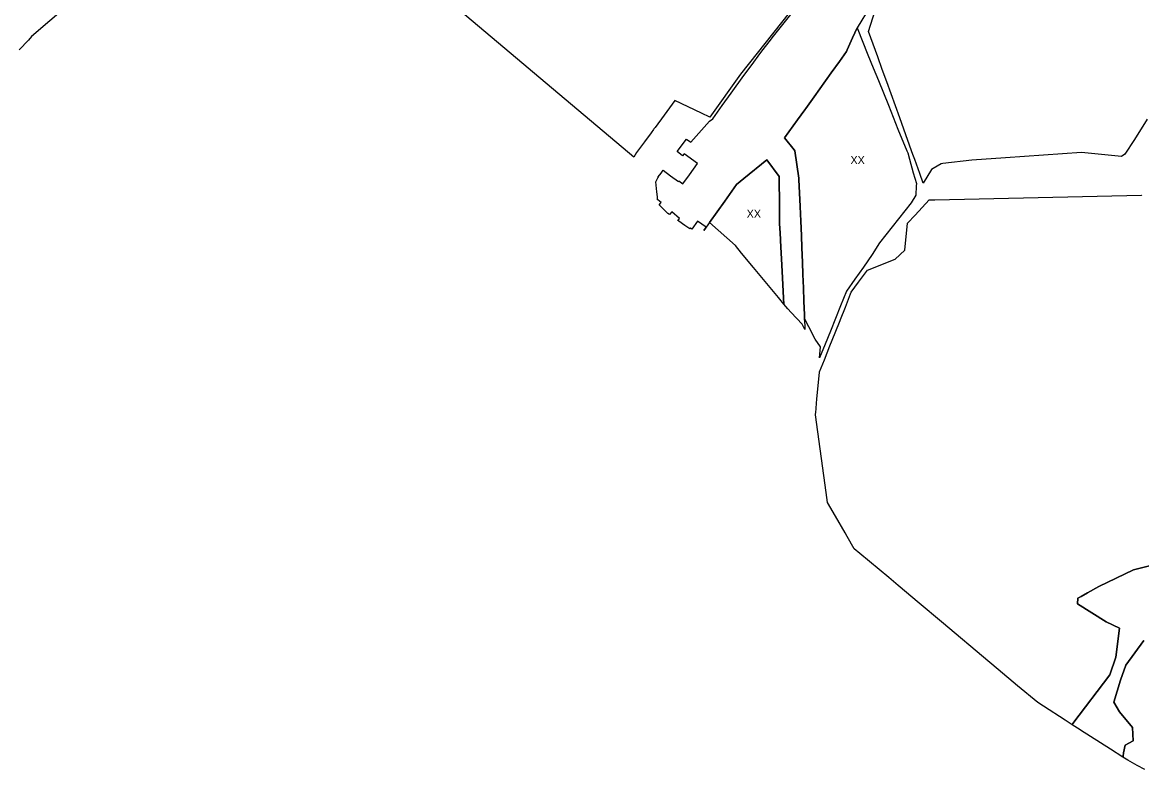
# Model space of a CAD drawing. Extents: x -537068 to -534056, y -1176840 to -1172401.
# Drawn here: x -536233 to -535534, y -1176810 to -1176344 of the extents above; entities that cross this region are included whole.
import ezdxf

# ---------------------------------------------------------------- set-up
doc = ezdxf.new("R2010")
doc.units = 0
for name, color, linetype in [('90550013', 7, 'Continuous'), ('90640013', 7, 'Continuous'), ('90710023', 7, 'Continuous'), ('90730013', 7, 'Continuous'), ('90750013', 7, 'Continuous')]:
    doc.layers.add(name, color=color, linetype=linetype)

msp = doc.modelspace()

# ---------------------------------------------------------------- linework, layer by layer
at = {"layer": '90550013'}
msp.add_lwpolyline([(-535530.06, -1176404.25), (-535538.13, -1176416.77), (-535544.12, -1176426.06), (-535546.07, -1176427.53), (-535571.1, -1176424.91), (-535618.53, -1176428.31), (-535639.55, -1176429.82), (-535657.85, -1176431.79), (-535658.77, -1176432.03), (-535663.81, -1176434.93), (-535664.74, -1176435.61), (-535669.94, -1176444.21), (-535672.16, -1176438.09), (-535675.32, -1176429.34), (-535676.47, -1176426.16), (-535677.31, -1176423.83), (-535682.13, -1176410.42), (-535684.69, -1176403.31), (-535687.39, -1176395.81), (-535692.81, -1176380.73), (-535695.55, -1176373.11), (-535698.43, -1176365.11), (-535704.11, -1176349.3), (-535700.03, -1176336.26)], dxfattribs=at)
for points in [[(-535674.59, -1176451.72), (-535677.45, -1176456.39), (-535697.41, -1176481.4), (-535701.92, -1176488.79), (-535707.35, -1176496.57), (-535712.69, -1176504.06), (-535718.01, -1176511.69), (-535721.59, -1176520.75), (-535724.82, -1176528.73), (-535727.94, -1176536.52), (-535731.3, -1176544.75), (-535734.75, -1176553.24), (-535734.17, -1176546.44), (-535737.41, -1176541.67), (-535741.44, -1176533.9), (-535743.29, -1176530.39), (-535743.81, -1176529.37), (-535744.12, -1176529.72), (-535744.24, -1176526.34), (-535744.54, -1176517.8), (-535744.83, -1176509.58), (-535745.13, -1176501.16), (-535745.4, -1176493.4), (-535745.72, -1176484.46), (-535746.06, -1176476.88), (-535746.47, -1176467.8), (-535746.87, -1176458.77), (-535747.63, -1176441.81), (-535747.75, -1176441), (-535750.23, -1176423.85), (-535750.71, -1176423.25), (-535756.58, -1176415.83), (-535748.51, -1176404.56), (-535743.99, -1176398.26), (-535743.37, -1176397.4), (-535738.21, -1176390.2), (-535727.54, -1176375.3), (-535722.39, -1176368.11), (-535717.9, -1176361.84), (-535717.46, -1176360.86), (-535714.08, -1176353.32), (-535711.31, -1176347.15), (-535704.53, -1176363.92), (-535701.24, -1176372.05), (-535698.04, -1176379.96), (-535691.75, -1176395.49), (-535688.76, -1176402.9), (-535685.77, -1176410.3), (-535680.29, -1176423.83), (-535679.7, -1176425.28), (-535678.58, -1176429.21), (-535676.19, -1176437.59), (-535674.3, -1176444.24), (-535674.36, -1176445.88)], [(-535756.96, -1176519.78), (-535760.42, -1176515.6), (-535768.68, -1176505.62), (-535775.96, -1176496.83), (-535783.4, -1176487.84), (-535787.33, -1176483.09), (-535803.54, -1176468.74), (-535798.79, -1176462.08), (-535793.96, -1176455.31), (-535786.56, -1176444.94), (-535781.98, -1176441.22), (-535767.68, -1176429.62), (-535760.01, -1176440.02), (-535760, -1176441.08), (-535759.81, -1176457.82), (-535759.72, -1176466.35), (-535759.68, -1176469.54), (-535759.38, -1176475.26), (-535758.91, -1176484.13), (-535758.51, -1176491.48), (-535758.08, -1176499.34), (-535757.64, -1176507.45), (-535757.17, -1176516.05)]]:
    msp.add_lwpolyline(points, close=True, dxfattribs=at)
at = {"layer": '90640013'}
for points in [[(-535703.24, -1176333.84), (-535711.31, -1176347.15), (-535714.08, -1176353.32), (-535717.46, -1176360.86), (-535717.9, -1176361.84), (-535722.39, -1176368.11), (-535727.54, -1176375.3), (-535738.21, -1176390.2), (-535743.37, -1176397.4), (-535743.99, -1176398.26), (-535748.51, -1176404.56), (-535756.58, -1176415.83), (-535750.71, -1176423.25), (-535750.23, -1176423.85), (-535747.75, -1176441), (-535747.63, -1176441.81), (-535746.87, -1176458.77), (-535746.47, -1176467.8), (-535746.06, -1176476.88), (-535745.72, -1176484.46), (-535745.4, -1176493.4), (-535745.13, -1176501.16), (-535744.83, -1176509.58), (-535744.54, -1176517.8), (-535744.24, -1176526.34), (-535744.12, -1176529.72), (-535743.96, -1176534.12), (-535743.9, -1176535.62), (-535744.79, -1176533.92), (-535745.69, -1176532.19), (-535752.39, -1176525), (-535754.65, -1176522.57), (-535756.96, -1176519.78), (-535757.17, -1176516.05), (-535757.64, -1176507.45), (-535758.08, -1176499.34), (-535758.51, -1176491.48), (-535758.91, -1176484.13), (-535759.38, -1176475.26), (-535759.68, -1176469.54), (-535759.72, -1176466.35), (-535759.81, -1176457.82), (-535760, -1176441.08), (-535760.01, -1176440.02), (-535767.68, -1176429.62), (-535781.98, -1176441.22), (-535786.56, -1176444.94), (-535793.96, -1176455.31), (-535798.79, -1176462.08), (-535803.54, -1176468.74), (-535807.04, -1176473.64), (-535805.66, -1176471.65), (-535810.99, -1176467.85), (-535814.51, -1176472.78), (-535815.39, -1176472.01), (-535815.79, -1176472.66), (-535818.84, -1176470.52), (-535820.4, -1176469.45), (-535823.43, -1176467.31), (-535823.13, -1176467.38), (-535822.14, -1176466.2), (-535826.97, -1176462.05), (-535828.46, -1176463.79), (-535829.43, -1176463.13), (-535834.99, -1176457.72), (-535833.71, -1176456.25), (-535835.85, -1176454.59), (-535836.06, -1176454.57), (-535835.98, -1176452.6), (-535836.3, -1176449.47), (-535836.91, -1176443.39), (-535835.7, -1176440.88), (-535835.37, -1176440.19), (-535835.49, -1176440.1), (-535833.72, -1176437.83), (-535832.45, -1176436.05), (-535827.81, -1176439.46), (-535822.86, -1176443.09), (-535822.57, -1176442.7), (-535820.19, -1176444.54), (-535815.92, -1176438.86), (-535810.92, -1176431.84), (-535819.35, -1176425.76), (-535820.26, -1176426.99), (-535823.71, -1176424.37), (-535817.82, -1176416.66), (-535815.25, -1176418.52), (-535803.56, -1176405.4), (-535801.4, -1176403.85), (-535795.48, -1176395.6), (-535789.9, -1176387.82), (-535782.02, -1176376.84), (-535777.52, -1176370.83), (-535771.34, -1176362.59), (-535764.83, -1176353.9), (-535764.34, -1176353.29), (-535752.68, -1176338.75)], [(-535510.43, -1176678.69), (-535538.74, -1176685.61), (-535560.3, -1176696.02), (-535567.5, -1176700.1), (-535571.31, -1176702.26), (-535573.45, -1176703.47), (-535573.71, -1176706.9), (-535555.67, -1176718.13), (-535547.5, -1176722.15), (-535549.75, -1176740.16), (-535553.5, -1176751.27), (-535576.51, -1176781.66), (-535576.91, -1176782.46), (-535581.44, -1176779.56), (-535594.9, -1176770.95), (-535598.48, -1176768.66), (-535611.07, -1176758.1), (-535623.22, -1176747.9), (-535628.42, -1176743.54), (-535658.68, -1176718.16), (-535672.54, -1176706.53), (-535685.74, -1176695.46), (-535691.56, -1176690.57), (-535709.56, -1176675.47), (-535713.04, -1176672.55), (-535717.46, -1176664.91), (-535718.78, -1176662.62), (-535724.88, -1176652.06), (-535729.7, -1176643.72), (-535730.58, -1176637.35), (-535737.27, -1176588.86), (-535737.19, -1176588), (-535737.15, -1176587.55), (-535736.36, -1176578.79), (-535735.61, -1176570.64), (-535734.85, -1176562.23), (-535734.72, -1176561.9), (-535731.73, -1176554.4), (-535728.31, -1176545.84), (-535725.02, -1176537.6), (-535721.93, -1176529.86), (-535721.7, -1176529.29), (-535718.6, -1176521.51), (-535715.34, -1176513.34), (-535714.92, -1176512.29), (-535710.34, -1176505.96), (-535705.52, -1176499.3), (-535704.9, -1176498.43), (-535704.8, -1176498.45), (-535687.44, -1176491.61), (-535681.47, -1176485.96), (-535679.85, -1176469.17), (-535675.08, -1176464.08), (-535666.19, -1176454.59), (-535662.84, -1176454.52), (-535533.71, -1176451.64), (-535533.49, -1176451.75)], [(-535531.67, -1176810.49), (-535536.29, -1176807.93), (-535542.25, -1176804.63), (-535545.34, -1176802.66), (-535545.23, -1176802.1), (-535544.85, -1176800.08), (-535543.92, -1176795.2), (-535538.92, -1176792.48), (-535539.33, -1176784.21), (-535547.44, -1176774.42), (-535550.96, -1176768.35), (-535546.78, -1176754.69), (-535543.5, -1176745.17), (-535532.18, -1176729.85)]]:
    msp.add_lwpolyline(points, dxfattribs=at)
at = {"layer": '90710023'}
msp.add_lwpolyline([(-536179.68, -1176311.98), (-536226.88, -1176352.57), (-536228.89, -1176354.7), (-536234.72, -1176360.87)], dxfattribs=at)
at = {"layer": '90730013'}
msp.add_lwpolyline([(-535532.18, -1176729.85), (-535543.5, -1176745.17), (-535546.78, -1176754.69), (-535550.96, -1176768.35), (-535547.44, -1176774.42), (-535539.33, -1176784.21), (-535538.92, -1176792.48), (-535543.92, -1176795.2), (-535544.85, -1176800.08), (-535545.23, -1176802.1), (-535545.34, -1176802.66), (-535553.07, -1176797.71), (-535571.69, -1176785.8), (-535572.06, -1176785.56), (-535573.58, -1176784.59), (-535576.91, -1176782.46), (-535576.51, -1176781.66), (-535553.5, -1176751.27), (-535549.75, -1176740.16), (-535547.5, -1176722.15), (-535555.67, -1176718.13), (-535573.71, -1176706.9), (-535573.45, -1176703.47), (-535571.31, -1176702.26), (-535567.5, -1176700.1), (-535560.3, -1176696.02), (-535538.74, -1176685.61), (-535510.43, -1176678.69)], dxfattribs=at)
at = {"layer": '90750013'}
msp.add_lwpolyline([(-535743.34, -1176324.33), (-535784.04, -1176376), (-535803.32, -1176402.89), (-535803.35, -1176402.91), (-535808.48, -1176400.44), (-535825.21, -1176392.4), (-535831.85, -1176401.58), (-535837.49, -1176409.37), (-535838.17, -1176410.22), (-535838.55, -1176410.7), (-535839.87, -1176412.68), (-535844.01, -1176418.3), (-535848.98, -1176425.04), (-535850.75, -1176427.84), (-535982.72, -1176316.41)], dxfattribs=at)

# ---------------------------------------------------------------- texts
at = {"layer": '90550013'}
for p in [(-535715.44, -1176432.18), (-535780.25, -1176465.73)]:
    msp.add_text('XX', height=5, rotation=0, dxfattribs=at).set_placement(p)

doc.saveas('drawing.dxf')
